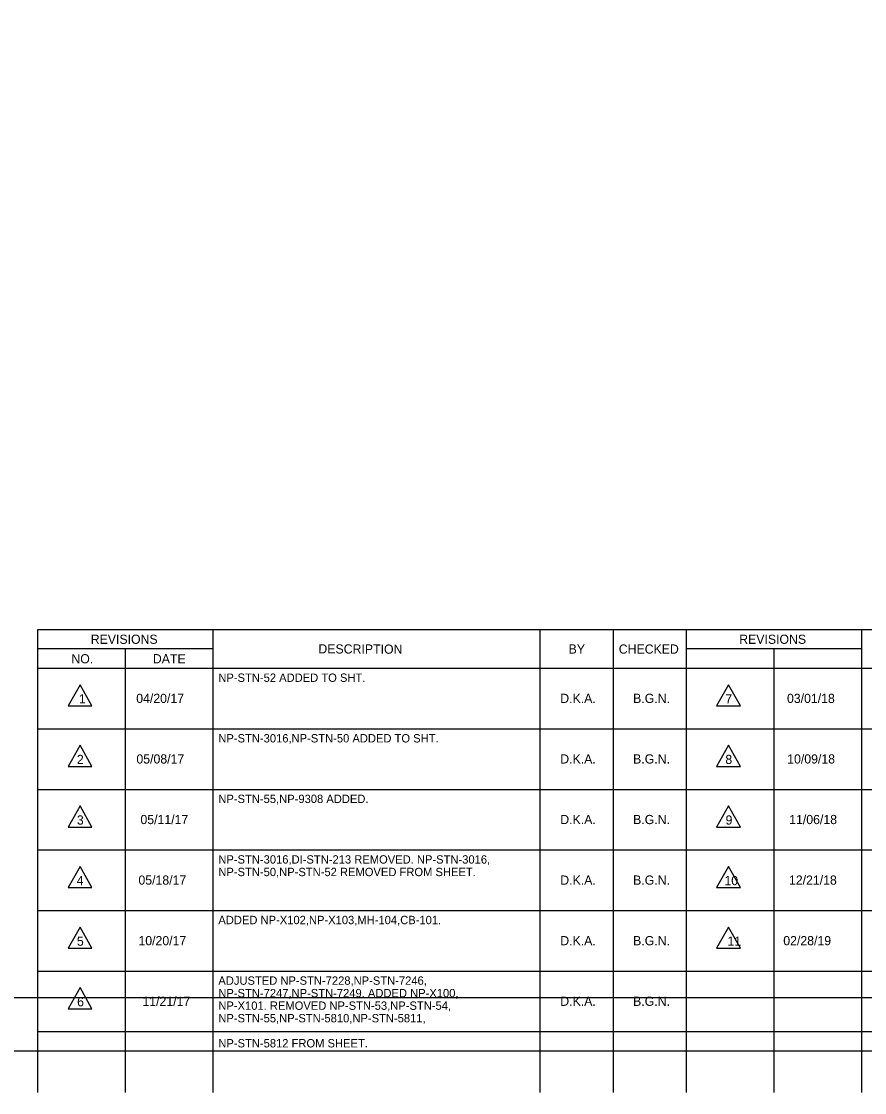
# Model space of a CAD drawing. Extents: x 260980 to 263829, y 322034 to 323393.
# Drawn here: x 261936 to 262340, y 322332 to 322845 of the extents above; entities that cross this region are included whole.
import ezdxf

# ---------------------------------------------------------------- set-up
doc = ezdxf.new("R2010")
doc.units = 0
for name, color, linetype in [('Level 23', 7, 'Continuous'), ('Level 5', 7, 'Continuous'), ('RD_SHT_TX', 7, 'Continuous')]:
    doc.layers.add(name, color=color, linetype=linetype)

msp = doc.modelspace()

# ---------------------------------------------------------------- linework, layer by layer
at = {"layer": 'Level 23'}
msp.add_lwpolyline([(261111.06, 323336.45), (262761.54, 323336.45), (262761.54, 322351.79), (261111.06, 322351.79)], close=True, dxfattribs=at)
msp.add_lwpolyline([(261111.06, 323336.45), (262761.54, 323336.45), (262761.54, 322351.79), (261111.06, 322351.79)], close=True, dxfattribs=at)
at = {"layer": 'Level 5'}
msp.add_lwpolyline([(261111.06, 323310.45), (262762.33, 323310.45), (262762.33, 322377.34), (261111.06, 322377.34)], close=True, dxfattribs=at)
at = {"layer": 'RD_SHT_TX'}
for p, q in [((261944.02, 322553.63), (262254.62, 322553.63)), ((261944.02, 322331.93), (261944.02, 322553.63)), ((262028.02, 322331.93), (262028.02, 322553.63)), ((262184.62, 322331.93), (262184.62, 322553.63)), ((262219.62, 322331.93), (262219.62, 322553.63)), ((262254.62, 322331.93), (262254.62, 322553.63)), ((262254.62, 322553.63), (262565.22, 322553.63)), ((262338.62, 322331.93), (262338.62, 322553.63)), ((262028.02, 322544.28), (261944.02, 322544.28)), ((261986.02, 322331.93), (261986.02, 322544.28)), ((262338.62, 322544.28), (262254.62, 322544.28)), ((262296.62, 322331.93), (262296.62, 322544.28)), ((262254.62, 322534.93), (261944.02, 322534.93)), ((262565.22, 322534.93), (262254.62, 322534.93)), ((261944.02, 322331.93), (261944.02, 322524.62)), ((261964.19, 322527.19), (261958.49, 322517.04)), ((261969.88, 322517.04), (261964.19, 322527.19)), ((262254.62, 322389.92), (262254.62, 322524.62)), ((262274.78, 322527.19), (262269.09, 322517.04)), ((262280.48, 322517.04), (262274.78, 322527.19)), ((261958.49, 322517.04), (261969.88, 322517.04)), ((262269.09, 322517.04), (262280.48, 322517.04)), ((262254.62, 322505.93), (261944.02, 322505.93)), ((262565.22, 322505.93), (262254.62, 322505.93)), ((261964.19, 322498.19), (261958.49, 322488.04)), ((261969.88, 322488.04), (261964.19, 322498.19)), ((262274.79, 322498.19), (262269.09, 322488.04)), ((262280.48, 322488.04), (262274.79, 322498.19)), ((261958.49, 322488.04), (261969.88, 322488.04)), ((262269.09, 322488.04), (262280.48, 322488.04)), ((262254.62, 322476.93), (261944.02, 322476.93)), ((262565.22, 322476.93), (262254.62, 322476.93)), ((261964.19, 322469.19), (261958.49, 322459.04)), ((261969.88, 322459.04), (261964.19, 322469.19)), ((262274.79, 322469.19), (262269.09, 322459.04)), ((262280.48, 322459.04), (262274.79, 322469.19)), ((261958.49, 322459.04), (261969.88, 322459.04)), ((262269.09, 322459.04), (262280.48, 322459.04)), ((262254.62, 322447.93), (261944.02, 322447.93)), ((262565.22, 322447.93), (262254.62, 322447.93)), ((261964.19, 322440.19), (261958.49, 322430.04)), ((261969.88, 322430.04), (261964.19, 322440.19)), ((262274.79, 322440.19), (262269.09, 322430.04)), ((262280.48, 322430.04), (262274.79, 322440.19)), ((261958.49, 322430.04), (261969.88, 322430.04)), ((262269.09, 322430.04), (262280.48, 322430.04)), ((262254.62, 322418.93), (261944.02, 322418.93)), ((262565.22, 322418.93), (262254.62, 322418.93)), ((261964.19, 322411.19), (261958.49, 322401.04)), ((261969.88, 322401.04), (261964.19, 322411.19)), ((262274.79, 322411.19), (262269.09, 322401.04)), ((262280.48, 322401.04), (262274.79, 322411.19)), ((261958.49, 322401.04), (261969.88, 322401.04)), ((262269.09, 322401.04), (262280.48, 322401.04)), ((262254.62, 322389.93), (261944.02, 322389.93)), ((262565.22, 322389.93), (262254.62, 322389.93)), ((261964.19, 322382.19), (261958.49, 322372.04)), ((261969.88, 322372.04), (261964.19, 322382.19)), ((261958.49, 322372.04), (261969.88, 322372.04)), ((262254.62, 322360.93), (261944.02, 322360.93)), ((262565.22, 322360.93), (262254.62, 322360.93))]:
    msp.add_line(p, q, dxfattribs=at)

# ---------------------------------------------------------------- texts
for s, p in [('REVISIONS', (261969.31, 322546.75)), ('REVISIONS', (262279.91, 322546.75)), ('CHECKED', (262222.22, 322542.05)), ('NO.', (261960.04, 322537.4)), ('1', (261963.65, 322518.22)), ('7', (262273.24, 322518.22)), ('2', (261962.68, 322489.22)), ('8', (262273.28, 322489.22)), ('3', (261962.68, 322460.22)), ('9', (262273.39, 322460.22)), ('4', (261962.57, 322431.22)), ('10', (262272.82, 322431.22)), ('5', (261962.68, 322402.22)), ('11', (262274.27, 322402.22)), ('6', (261962.79, 322373.22))]:
    msp.add_text(s, height=4.4, dxfattribs=at).set_placement(p)
for s, height, rotation, p in [('DESCRIPTION', 4.4083, 359.7246, (262078.32, 322542.17)), ('BY', 4.408, 359.7246, (262198.18, 322542.09)), ('DATE', 4.408, 359.7246, (261999.05, 322537.43)), ('NP-STN-52 ADDED TO SHT.', 4, 360, (262030.43, 322528.54)), ('04/20/17', 4.4, 360, (261991.1, 322518.45)), ('D.K.A.', 4.4, 360, (262194.21, 322518.45)), ('B.G.N.', 4.4, 360, (262229.09, 322518.45)), ('03/01/18', 4.4, 360, (262302.79, 322518.45)), ('NP-STN-3016,NP-STN-50 ADDED TO SHT.', 4, 360, (262030.43, 322499.54)), ('05/08/17', 4.4, 360, (261991.2, 322489.45)), ('D.K.A.', 4.4, 360, (262194.21, 322489.45)), ('B.G.N.', 4.4, 360, (262229.09, 322489.45)), ('10/09/18', 4.4, 360, (262302.9, 322489.45)), ('NP-STN-55,NP-9308 ADDED.', 4, 360, (262030.43, 322470.54)), ('05/11/17', 4.4, 360, (261993.12, 322460.45)), ('D.K.A.', 4.4, 360, (262194.21, 322460.45)), ('B.G.N.', 4.4, 360, (262229.09, 322460.45)), ('11/06/18', 4.4, 360, (262303.86, 322460.45)), ('NP-STN-3016,DI-STN-213 REMOVED. NP-STN-3016,', 4, 360, (262030.43, 322441.54)), ('05/18/17', 4.4, 360, (261992.16, 322431.45)), ('NP-STN-50,NP-STN-52 REMOVED FROM SHEET.', 4, 360, (262030.43, 322435.54)), ('D.K.A.', 4.4, 360, (262194.21, 322431.45)), ('B.G.N.', 4.4, 360, (262229.09, 322431.45)), ('12/21/18', 4.4, 360, (262303.75, 322431.45)), ('ADDED NP-X102,NP-X103,MH-104,CB-101.', 4, 360, (262030.43, 322412.54)), ('10/20/17', 4.4, 360, (261992.16, 322402.45)), ('D.K.A.', 4.4, 360, (262194.21, 322402.45)), ('B.G.N.', 4.4, 360, (262229.09, 322402.45)), ('02/28/19', 4.4, 360, (262301.02, 322402.45)), ('ADJUSTED NP-STN-7228,NP-STN-7246,', 4, 360, (262030.43, 322383.54)), ('NP-STN-7247,NP-STN-7249. ADDED NP-X100,', 4, 360, (262030.43, 322377.54)), ('11/21/17', 4.4, 360, (261994.07, 322373.45)), ('NP-X101. REMOVED NP-STN-53,NP-STN-54,', 4, 360, (262030.43, 322371.54)), ('D.K.A.', 4.4, 360, (262194.21, 322373.45)), ('B.G.N.', 4.4, 360, (262229.09, 322373.45)), ('NP-STN-55,NP-STN-5810,NP-STN-5811,', 4, 360, (262030.43, 322365.54)), ('NP-STN-5812 FROM SHEET. ', 4, 360, (262030.43, 322353.54))]:
    msp.add_text(s, height=height, rotation=rotation, dxfattribs=at).set_placement(p)

doc.saveas('drawing.dxf')
